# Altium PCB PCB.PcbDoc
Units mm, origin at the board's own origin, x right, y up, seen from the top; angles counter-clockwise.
Board outline 82.53 x 49.5 mm, 2 copper layers (Top Layer, Bottom Layer); 57 components, 42 nets, 216 pads, 120 vias.
Unrouted connection lines stored in the file: 2.
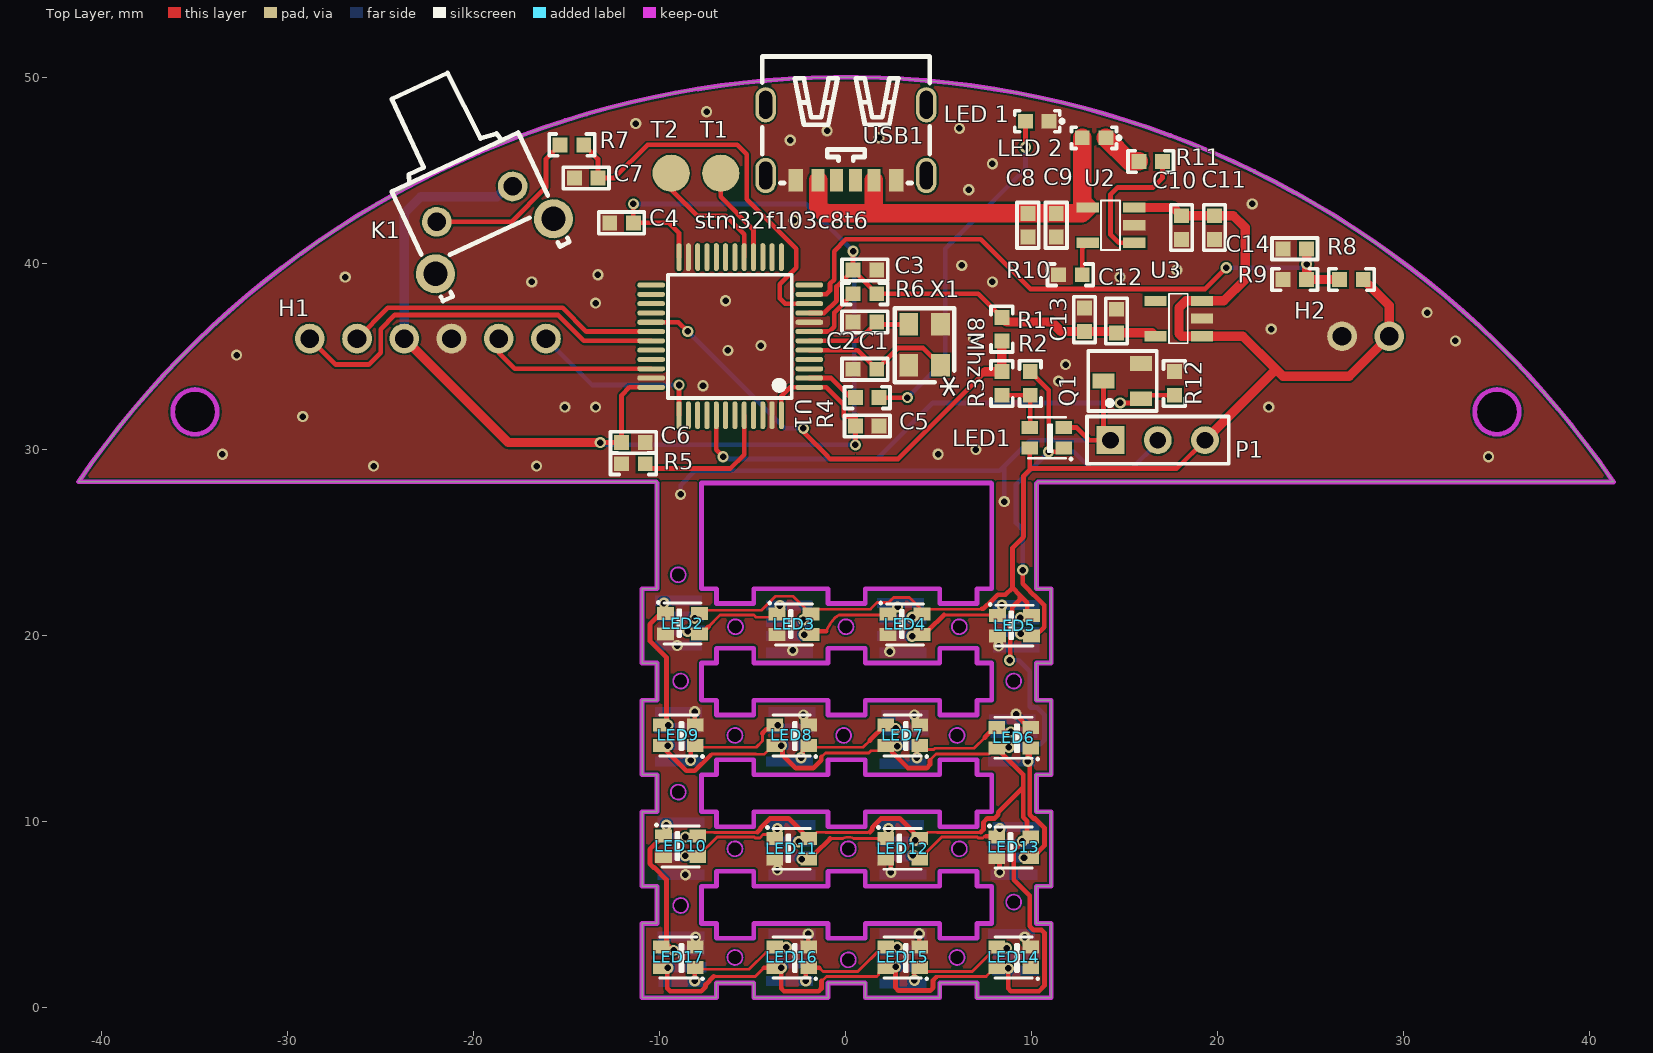
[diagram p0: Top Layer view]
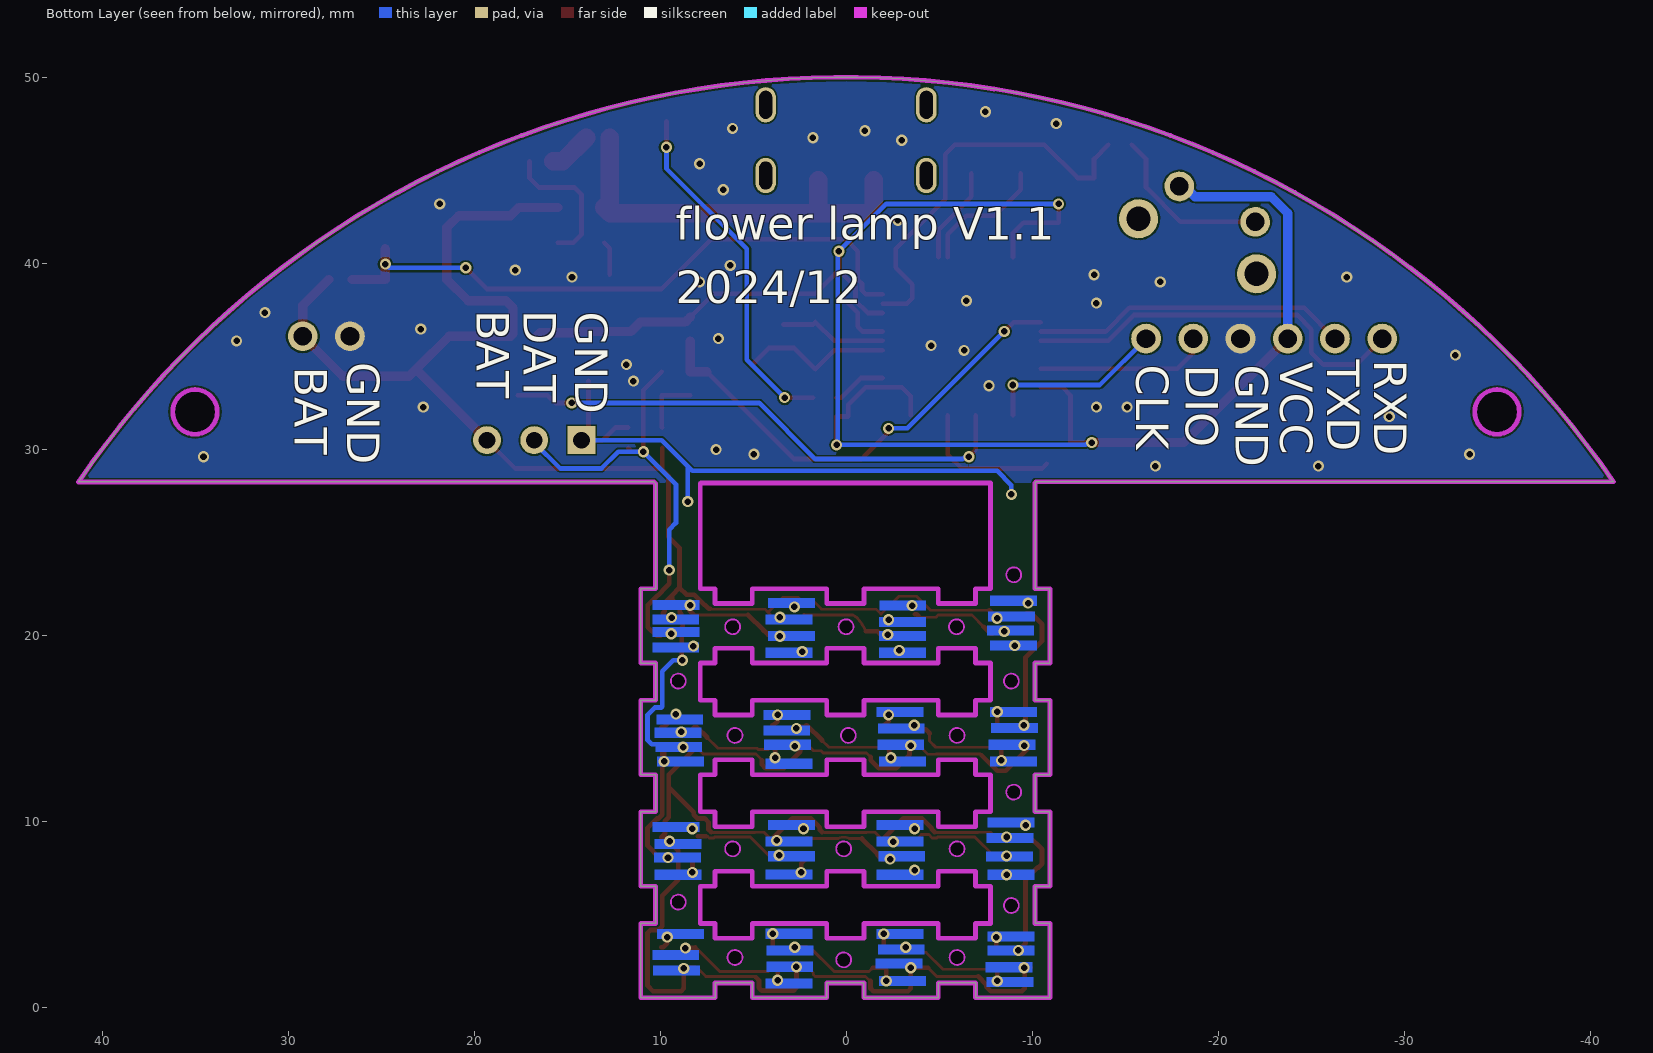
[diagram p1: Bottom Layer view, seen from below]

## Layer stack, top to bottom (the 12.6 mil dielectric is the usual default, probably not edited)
Top Solder: solder mask 0.0102, Solder Resist, Dk 3.5
Top Layer: signal copper 0.0356
Dielectric 1: dielectric 0.32, FR-4, Dk 4.8
Bottom Layer: signal copper 0.0356
Bottom Solder: solder mask 0.0102, Solder Resist, Dk 3.5

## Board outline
-10.962,0.497 -10.962,4.497 -10.162,4.497 -10.162,6.497 -10.962,6.497 -10.962,10.497 -10.162,10.497 -10.162,12.497 -10.962,12.497 -10.962,16.497 -10.162,16.497 -10.162,18.497 -10.962,18.497 -10.962,22.497 -10.162,22.497 -10.162,28.192 -10.206,28.236 -41.264,28.236 cw(c0,0) 41.266,28.233 10.326,28.233 10.238,28.145 10.238,22.497 11.038,22.497 11.038,18.497 10.238,18.497 10.238,16.497 11.038,16.497 11.038,12.497 10.238,12.497 10.238,10.497 11.038,10.497 11.038,6.497 10.238,6.497 10.238,4.497 11.038,4.497 11.038,0.497 7.038,0.497 7.038,1.297 5.038,1.297 5.038,0.497 1.038,0.497 1.038,1.297 -0.962,1.297 -0.962,0.497 -4.962,0.497 -4.962,1.297 -6.962,1.297 -6.962,0.497
cut-out: -9.417,23.241 ccw(c-9.017,23.241) -9.017,22.841 ccw(c-9.017,23.241) -8.617,23.241 ccw(c-9.017,23.241) -9.017,23.641 ccw(c-9.017,23.241)
cut-out: -0.273,2.54 ccw(c0.127,2.54) 0.127,2.14 ccw(c0.127,2.54) 0.527,2.54 ccw(c0.127,2.54) 0.127,2.94 ccw(c0.127,2.54)
cut-out: -6.369,2.667 ccw(c-5.969,2.667) -5.969,2.267 ccw(c-5.969,2.667) -5.569,2.667 ccw(c-5.969,2.667) -5.969,3.067 ccw(c-5.969,2.667)
cut-out: 5.569,2.667 ccw(c5.969,2.667) 5.969,2.267 ccw(c5.969,2.667) 6.369,2.667 ccw(c5.969,2.667) 5.969,3.067 ccw(c5.969,2.667)
cut-out: 8.617,5.644 ccw(c9.017,5.644) 9.017,5.244 ccw(c9.017,5.644) 9.417,5.644 ccw(c9.017,5.644) 9.017,6.044 ccw(c9.017,5.644)
cut-out: 5.696,8.509 ccw(c6.096,8.509) 6.096,8.109 ccw(c6.096,8.509) 6.496,8.509 ccw(c6.096,8.509) 6.096,8.909 ccw(c6.096,8.509)
cut-out: -0.273,8.509 ccw(c0.127,8.509) 0.127,8.109 ccw(c0.127,8.509) 0.527,8.509 ccw(c0.127,8.509) 0.127,8.909 ccw(c0.127,8.509)
cut-out: -6.369,8.509 ccw(c-5.969,8.509) -5.969,8.109 ccw(c-5.969,8.509) -5.569,8.509 ccw(c-5.969,8.509) -5.969,8.909 ccw(c-5.969,8.509)
cut-out: 8.617,17.526 ccw(c9.017,17.526) 9.017,17.126 ccw(c9.017,17.526) 9.417,17.526 ccw(c9.017,17.526) 9.017,17.926 ccw(c9.017,17.526)
cut-out: 5.569,14.605 ccw(c5.969,14.605) 5.969,14.205 ccw(c5.969,14.605) 6.369,14.605 ccw(c5.969,14.605) 5.969,15.005 ccw(c5.969,14.605)
cut-out: -0.527,14.605 ccw(c-0.127,14.605) -0.127,14.205 ccw(c-0.127,14.605) 0.273,14.605 ccw(c-0.127,14.605) -0.127,15.005 ccw(c-0.127,14.605)
cut-out: -6.369,14.605 ccw(c-5.969,14.605) -5.969,14.205 ccw(c-5.969,14.605) -5.569,14.605 ccw(c-5.969,14.605) -5.969,15.005 ccw(c-5.969,14.605)
cut-out: -9.29,5.461 ccw(c-8.89,5.461) -8.89,5.061 ccw(c-8.89,5.461) -8.49,5.461 ccw(c-8.89,5.461) -8.89,5.861 ccw(c-8.89,5.461)
cut-out: -9.417,11.557 ccw(c-9.017,11.557) -9.017,11.157 ccw(c-9.017,11.557) -8.617,11.557 ccw(c-9.017,11.557) -9.017,11.957 ccw(c-9.017,11.557)
cut-out: -9.29,17.526 ccw(c-8.89,17.526) -8.89,17.126 ccw(c-8.89,17.526) -8.49,17.526 ccw(c-8.89,17.526) -8.89,17.926 ccw(c-8.89,17.526)
cut-out: 5.696,20.447 ccw(c6.096,20.447) 6.096,20.047 ccw(c6.096,20.447) 6.496,20.447 ccw(c6.096,20.447) 6.096,20.847 ccw(c6.096,20.447)
cut-out: -0.4,20.447 ccw(c0,20.447) 0,20.047 ccw(c0,20.447) 0.4,20.447 ccw(c0,20.447) 0,20.847 ccw(c0,20.447)
cut-out: -6.34,20.447 ccw(c-5.94,20.447) -5.94,20.047 ccw(c-5.94,20.447) -5.54,20.447 ccw(c-5.94,20.447) -5.94,20.847 ccw(c-5.94,20.447)
cut-out: 33.8,32 ccw(c35,32) 35,30.8 ccw(c35,32) 36.2,32 ccw(c35,32) 35,33.2 ccw(c35,32)
cut-out: -35,30.8 cw(c-35,32) -36.2,32 cw(c-35,32) -35,33.2 cw(c-35,32) -33.8,32 cw(c-35,32)
cut-out: -6.962,21.697 -4.962,21.697 -4.962,22.497 -0.962,22.497 -0.962,21.697 1.038,21.697 1.038,22.497 5.038,22.497 5.038,21.697 7.038,21.697 7.038,22.497 7.838,22.497 7.838,28.158 7.817,28.179 -7.762,28.179 -7.762,22.497 -6.962,22.497
cut-out: -7.762,4.497 -6.962,4.497 -6.962,3.697 -4.962,3.697 -4.962,4.497 -0.962,4.497 -0.962,3.697 1.038,3.697 1.038,4.497 5.038,4.497 5.038,3.697 7.038,3.697 7.038,4.497 7.838,4.497 7.838,6.497 7.038,6.497 7.038,7.297 5.038,7.297 5.038,6.497 1.038,6.497 1.038,7.297 -0.962,7.297 -0.962,6.497 -4.962,6.497 -4.962,7.297 -6.962,7.297 -6.962,6.497 -7.762,6.497
cut-out: -4.962,9.697 -4.962,10.497 -0.962,10.497 -0.962,9.697 1.038,9.697 1.038,10.497 5.038,10.497 5.038,9.697 7.038,9.697 7.038,10.497 7.838,10.497 7.838,12.497 7.038,12.497 7.038,13.297 5.038,13.297 5.038,12.497 1.038,12.497 1.038,13.297 -0.962,13.297 -0.962,12.497 -4.962,12.497 -4.962,13.297 -6.962,13.297 -6.962,12.497 -7.762,12.497 -7.762,10.497 -6.962,10.497 -6.962,9.697
cut-out: -7.762,16.497 -6.962,16.497 -6.962,15.697 -4.962,15.697 -4.962,16.497 -0.962,16.497 -0.962,15.697 1.038,15.697 1.038,16.497 5.038,16.497 5.038,15.697 7.038,15.697 7.038,16.497 7.838,16.497 7.838,18.497 7.038,18.497 7.038,19.297 5.038,19.297 5.038,18.497 1.038,18.497 1.038,19.297 -0.962,19.297 -0.962,18.497 -4.962,18.497 -4.962,19.297 -6.962,19.297 -6.962,18.497 -7.762,18.497

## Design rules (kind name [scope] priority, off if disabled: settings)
Clearance [All] p1: gap=0.1 ignorepadtopadclearanceinfootprint=FALSE except(0: Arc-Hole Track-Hole SMDPad-Hole THPad-Hole Via-Hole Fill-Hole Poly-Hole Region-Hole Text-Hole; 0.102: Arc-Arc Arc-Track Arc-SMDPad Arc-THPad Track-Track Track-SMDPad Track-THPad SMDPad-SMDPad SMDPad-THPad THPad-THPad; 0.127: Arc-Via Track-Via SMDPad-Via SMDPad-Text THPad-Via Via-Via; 0.254: Arc-Text Track-Text THPad-Text Via-Text Fill-Text Poly-Text Region-Text Text-Text)
DiffPairsRouting [All] p1: maxlimit=0.254 minlimit=0.15 mostfreqgap=0.254 toplayer_minwidth=0.2 toplayer_maxwidth=0.381 toplayer_prefwidth=0.25 bottomlayer_minwidth=0.2 bottomlayer_maxwidth=0.381 bottomlayer_prefwidth=0.25 maxuncoupledlength=12.7
HoleSize [All] p1: absolutevalues=TRUE maxlimit=30 minlimit=0.025 maxpercent=80.000 minpercent=20.000
HoleToHoleClearance [All] p1: gap=0.152 allowstackedmicrovias=TRUE
MinimumSolderMaskSliver [All] p1: minsoldermaskwidth=0
PlaneClearance [All] p1: clearance=0.254
PlaneConnect [All] p1: planeconnectstyle=Direct reliefexpansion=0.508 reliefentries=4 reliefconductorwidth=0.254 reliefairgap=0.254
PolygonConnect [All] p1: connectstyle=Direct reliefconductorwidth=0.254 reliefentries=4 polygonreliefangle="90 Angle" airgapwidth=0.254
RoutingVias [All] p1: holewidth=0.711 width=1.27 viastyle="Through Hole" minholewidth=0.3 minwidth=0.5 maxholewidth=30 maxwidth=30
SilkToSilkClearance [All] p1: silktosilkclearance=0
SilkToSolderMaskClearance [IsPad] p1: minsilkscreentomaskgap=0 clearancetoexposedcopper=TRUE
SolderMaskExpansion [All] p1: expansion=0.102 istentingtop=FALSE
Width [All] p1: maxlimit=3 minlimit=0.1 preferedwidth=0.254
22 further rules are at their usual default settings.

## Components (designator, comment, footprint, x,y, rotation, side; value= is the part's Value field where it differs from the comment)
C1 "12pF" CC1608-0603 1.016,34.29 r0 top
C2 "12pF" CC1608-0603 1.016,36.83 r0 top
C3 "100NF" CC1608-0603 1.016,39.624 r180 top
C4 "100NF" CC1608-0603 -12.065,42.164 r0 top
C5 "100NF" CC1608-0603 1.143,31.242 r180 top
C6 "100NF" CC1608-0603 -11.43,30.353 r180 top
C7 "12pF" CC1608-0603 -13.97,44.577 r0 top
C8 "1UF" CC1608-0603 9.779,42.037 r90 top
C9 "100NF" CC1608-0603 11.303,42.037 r90 top
C10 "1UF" CC1608-0603 18.034,41.91 r90 top
C11 "100NF" CC1608-0603 19.812,41.91 r90 top
C12 "1UF" CC1608-0603 14.544,36.885 r270 top
C13 "100NF" CC1608-0603 12.827,36.957 r270 top
C14 "100PF" CC1608-0603 24.13,40.767 r0 top
H1 "Header_6P_Curved" Header_2_54_6PW -28.829,35.941 r0 top
H2 "Header_2P_Curved" Header_2_54_2PW 26.67,36.068 r0 top
K1 "SW-TH_4P_H" SW-TH_KH-6X6X7H-ZJ -19.431,42.037 r25 top locked
LED1 "WS2812B-2020" WS2812B-2020 10.795,30.607 r180 top
LED2 "WS2812B-2020" WS2812B-2020 -8.789,20.616 r0 top
LED3 "WS2812B-2020" WS2812B-2020 -2.794,20.574 r0 top
LED4 "WS2812B-2020" WS2812B-2020 3.175,20.574 r0 top
LED5 "WS2812B-2020" WS2812B-2020 9.061,20.507 r0 top
LED6 "WS2812B-2020" WS2812B-2020 9.017,14.478 r180 top
LED7 "WS2812B-2020" WS2812B-2020 3.048,14.605 r180 top
LED8 "WS2812B-2020" WS2812B-2020 -2.921,14.605 r180 top
LED9 "WS2812B-2020" WS2812B-2020 -9.017,14.605 r180 top
LED10 "WS2812B-2020" WS2812B-2020 -8.89,8.636 r0 top
LED11 "WS2812B-2020" WS2812B-2020 -2.921,8.509 r0 top
LED12 "WS2812B-2020" WS2812B-2020 3.048,8.509 r0 top
LED13 "WS2812B-2020" WS2812B-2020 9.017,8.585 r0 top
LED14 "WS2812B-2020" WS2812B-2020 9.017,2.667 r180 top
LED15 "WS2812B-2020" WS2812B-2020 3.048,2.667 r180 top
LED16 "WS2812B-2020" WS2812B-2020 -2.921,2.667 r180 top
LED17 "WS2812B-2020" WS2812B-2020 -9.017,2.667 r180 top
"LED 1" "LED 0603" "LED 0603" 10.287,47.625 r0 top
"LED 2" "LED 0603" "LED 0603" 13.335,46.736 r0 top
P1 "Header 3" HDR1X3 14.224,30.48 r0 top
Q1 "SI2302" SOT-23 15.863,32.705 r90 top
R1 "10K" CR1608-0603 8.382,36.449 r270 top
R2 "0R" CR1608-0603 9.906,33.528 r90 top
R3 "0R" CR1608-0603 8.382,33.528 r270 top
R4 "1K" CR1608-0603 1.143,32.766 r180 top
R5 "10K" CR1608-0603 -11.43,29.21 r0 top
R6 "10K" CR1608-0603 1.016,38.354 r180 top
R7 "1K" CR1608-0603 -14.732,46.355 r180 top
R8 "10K" CR1608-0603 27.178,39.116 r0 top
R9 "10K" CR1608-0603 24.13,39.116 r0 top
R10 "2K" CR1608-0603 12.065,39.37 r0 top
R11 "2K" CR1608-0603 16.383,45.466 r180 top
R12 "10K" CR1608-0603 17.653,33.528 r90 top
T1 "test" test -6.731,44.831 r0 top
T2 "test" test -9.398,44.831 r0 top
U1 "STM32F103C8T6" LQFP-48 -6.223,36.068 r90 top locked
U2 "TP4054" SOT23-5 15.494,42.992 r270 top
U3 "RT9013-33GB" SOT23-5 19.137,37.973 r270 top
USB1 "TYPE_C_SMD_6P" TYPE-C-SMD_TYPE-C-6P 0,46.482 r180 top locked
X1 "3225_8M" XTAL-3225 3.38,34.503 r90 top

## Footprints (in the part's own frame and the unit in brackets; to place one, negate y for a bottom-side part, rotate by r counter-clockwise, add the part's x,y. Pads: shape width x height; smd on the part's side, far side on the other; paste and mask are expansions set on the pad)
CC1608-0603 [mm]
  rect 0.8x0.8 smd: 1(-0.635,0) 2(0.635,0)
  silkscreen extent -1.23,-0.58 1.23,0.58, body extent -0.8,-0.4 0.8,0.4, height 0.3
CR1608-0603 [mm]
  rect 0.8x0.8 smd: 1(-0.635,0) 2(0.635,0)
  silkscreen extent -1.23,-0.58 1.23,0.58, body extent -0.8,-0.4 0.8,0.4, height 0.45
HDR1X3 [mm] "Connector; Header; 3 Position"
  rect 1.5x1.5 hole 0.9: 1(0,0)
  round 1.5 hole 0.9: 2(2.54,0) 3(5.08,0)
  silkscreen extent -1.27,-1.27 6.35,2.14, body extent -1.27,-1.27 6.35,1.27, height 8.54
Header_2_54_2PW [mm] "弯的排针"
  round 1.6 hole 1: 1(0,0) 2(2.54,0)
  body extent -2.52,-7.47 5.18,0.38, height 5.8
Header_2_54_6PW [mm] "6P弯针"
  round 1.6 hole 1: 1(0,0) 2(2.54,0) 3(5.08,0) 4(7.62,0) 5(10.16,0) 6(12.7,0)
  body extent -2.56,-7.48 15.3,0.37, height 5.8
"LED 0603" [mm]
  rect 0.8x0.8 smd: 1(-0.635,0) 2(0.635,0)
  silkscreen extent -1.21,-0.57 1.4,0.57, body extent -0.8,-0.4 0.8,0.4, height 0.6
LQFP-48 [mm]
  oval 0.27x1.5 smd: 1(-2.75,-4.25) 2(-2.25,-4.25) 3(-1.75,-4.25) 4(-1.25,-4.25) 5(-0.75,-4.25) 6(-0.25,-4.25) 7(0.25,-4.25) 8(0.75,-4.25) 9(1.25,-4.25) 10(1.75,-4.25) 11(2.25,-4.25) 12(2.75,-4.25) 25(2.75,4.25) 26(2.25,4.25) 27(1.75,4.25) 28(1.25,4.25) 29(0.75,4.25) 30(0.25,4.25) 31(-0.25,4.25) 32(-0.75,4.25) 33(-1.25,4.25) 34(-1.75,4.25) 35(-2.25,4.25) 36(-2.75,4.25)
  oval 1.5x0.27 smd: 13(4.25,-2.75) 14(4.25,-2.25) 15(4.25,-1.75) 16(4.25,-1.25) 17(4.25,-0.75) 18(4.25,-0.25) 19(4.25,0.25) 20(4.25,0.75) 21(4.25,1.25) 22(4.25,1.75) 23(4.25,2.25) 24(4.25,2.75) 37(-4.25,2.75) 38(-4.25,2.25) 39(-4.25,1.75) 40(-4.25,1.25) 41(-4.25,0.75) 42(-4.25,0.25) 43(-4.25,-0.25) 44(-4.25,-0.75) 45(-4.25,-1.25) 46(-4.25,-1.75) 47(-4.25,-2.25) 48(-4.25,-2.75)
  silkscreen extent -3.33,-3.31 3.3,3.34, body extent -4.47,-4.54 4.53,4.46, height 1.56
SOT23-5 [mm] "适用于MIC5205"
  rect 0.55x1.2 smd: 1(1.905,0) 2(0.955,0) 3(0.005,0) 4(0.005,-2.5) 5(1.905,-2.5)
  silkscreen extent -0.38,-1.78 2.29,-0.76, body extent -0.6,-2.82 2.5,0.38, height 1.45
SOT-23 [mm]
  rect 0.8x1.2 smd: 1(0,0) 2(1.905,0) 3(0.95,2.02)
  silkscreen extent -0.66,-0.84 2.57,2.84, body extent -0.61,-0.23 2.39,2.27, height 1.05
SW-TH_KH-6X6X7H-ZJ [mm]
  round 1.6 hole 1 paste+0 mask+0.05: 1(2.25,1.25) 2(-2.25,1.25)
  round 2.1 hole 1.3 paste+0 mask+0.05: 3(3.5,-1.25) 4(-3.5,-1.25)
  silkscreen extent -3.75,-2.75 3.75,8.25, body extent -3.75,-2.48 3.75,5.67, height 7.5
test [mm]
  round 2 smd: 0(0,0)
TYPE-C-SMD_TYPE-C-6P [mm]
  oval 1.1x1.9 hole 0.7 slot 1.5 at 90 deg paste+0 mask+0.051: 7(-4.32,-2.025) 7(-4.32,1.775) 7(4.32,-2.025) 7(4.32,1.775)
  rect 0.7x1.2 smd paste-100 mask+0.051: A5(-0.5,2.025) A9(1.5,2.025) B5(0.5,2.025) B9(-1.5,2.025)
  rect 0.8x1.2 smd paste-100 mask+0.051: A12(2.7,2.025) B12(-2.7,2.025)
  silkscreen extent -4.5,-4.63 4.5,2.18, body extent -4.44,-4.47 4.49,2.43, height 3.18
WS2812B-2020 [mm]
  rect 0.9x0.7 smd paste+0 mask+0.051: 1(-0.915,0.55) 2(-0.915,-0.55) 3(0.915,-0.55) 4(0.915,0.55)
  silkscreen extent -1.3,-1.1 1,1.15, body extent -1.1,-1 1.1,1, height 0.84
XTAL-3225 [mm]
  rect 1.2x1 smd: 1(0,-1.7) 2(2.2,-1.7) 3(2.2,0) 4(0,0)
  silkscreen extent -0.91,-2.44 3.07,0.76, body extent -0.43,-2.15 2.77,0.35, height 0.61

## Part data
C1 C2 C3 C4 C5 C6 C7 C8 C9 C10 C11 C12 C13 C14: library part "Cap Chip 0603", "0603封装的电容"
H1: "弯的6P排针"
H2: "弯的2P排针"
K1: "卧式轻触开关"
LED1 LED2 LED3 LED4 LED5 LED6 LED7 LED8 LED9 LED10 LED11 LED12 LED13 LED14 LED15 LED16 LED17: JLCPCB Part Class="Extended Part", Manufacturer=worldsemi
P1: "Header, 3-Pin"
Q1: "N沟道  / 漏源电压(Vdss) 20V  / 连续漏极电流(Id) 2.8A  / 功率(Pd) 900mW  / 导通电阻(RDS(on)@Vgs,Id) 55mΩ@4.5V,2.8A  / 阈值电压(Vgs(th)@Id) 1.2V@250uA  / 输入电容(Ciss@Vds) 260pF@10V", JLCPCB Part Class="Extended Part", Manufacturer=TWGMC(台湾迪嘉), Manufacturer Part=SI2306
R1 R2 R3 R4 R5 R6 R7 R8 R9 R10 R11 R12: library part "Resistor Chip 0603", "0603封装电阻"
T1 T2: "测试点"
U1: JLCPCB Part Class="Basic Part", Manufacturer=ST(意法半导体)
U2: "迷你充电IC SOT-23-5"
U3: "LDO 2.2-5.2V IN 500Ma OUT SOT23-5"
USB1: JLCPCB Part Class="Extended Part", Manufacturer=null
X1: library part "XTAL 3225", "3225封装的晶振"

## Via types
v1: diameter 0.6, hole 0.35, Top Layer to Bottom Layer, tented both sides, 120 vias

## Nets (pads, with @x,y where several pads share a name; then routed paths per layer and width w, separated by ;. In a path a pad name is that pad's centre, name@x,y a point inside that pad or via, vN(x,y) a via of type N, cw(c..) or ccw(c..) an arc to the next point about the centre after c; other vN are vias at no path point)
5V: "LED 2.1" C8.2 C9.2 U2.4 USB1.A9 USB1.B9 | length 22
  Top Layer w1: USB1.A9 -1.5,43.029 -1.143,42.672 1.778,42.672 ; USB1.B9 1.5,42.95 1.778,42.672 ; 12.7,46.736 12.7,43.281 U2.4 12.679,42.672 C9.2 C8.2 1.778,42.672
ADCIN1: C14.2 R8.1 R9.2 U1.11 | length 34.2
  Top Layer w0.254: U1.11 -1.052,38.318 -0.864,38.506 -0.864,38.882 -0.635,39.111 -0.635,40.64 0,41.275 7.239,41.275 9.906,38.608 19.304,38.608 v1(20.447,39.751)
  Top Layer w0.5: C14.2 v1(24.765,39.941) R9.2 R8.1
  Bottom Layer w0.254: v1(20.447,39.751) 24.575,39.751 v1(24.765,39.941)
BAT: C10.2 C11.2 H2.2 LED1.4 LED2.4 LED3.4 LED4.4 LED5.4 LED6.4 LED7.4 LED8.4 LED9.4 LED10.4 LED11.4 LED12.4 LED13.4 LED14.4 LED15.4 LED16.4 LED17.4 P1.3 R8.2 U2.3 U3.1 U3.3 | length 175.3
  Top Layer w0.15: LED10.4 -7.763,9.398 -7.092,9.398 -7.088,9.393 -4.836,9.393 -4.832,9.398 -4.758,9.398 ; LED2.4@-7.704,21.336 -4.547,21.336 -3.793,22.089 -2.844,22.089 LED3.4 -1.61,21.393 1.313,21.393 1.665,21.746 2.297,21.746 2.57,22.018 3.406,22.018 LED4.4@4.195,21.229 ; -7.302,13.525 -7.227,13.601 -4.836,13.601 -4.825,13.589 -4.402,13.589 -3.936,14.055 LED8.4 ; -7.111,1.651 -4.879,1.651 -4.413,2.117 ; LED11.4 -1.906,9.059 -1.567,9.398 -1.092,9.398 -1.088,9.393 1.164,9.393 1.168,9.398 1.286,9.398 ; -1.327,13.443 -1.104,13.666 1.222,13.666 1.335,13.78 1.758,13.78 2.033,14.055 LED7.4 ; -1.318,1.397 -1.291,1.397 -1.037,1.651 1.667,1.651 1.758,1.742 1.758,1.842 2.033,2.117 LED15.4 ; LED12.4 4.063,9.059 4.402,9.398 4.908,9.398 4.912,9.393 7.164,9.393 7.168,9.398 7.242,9.398 ; LED4.4 LED4.4@4.195,21.229 ; 4.513,13.275 4.839,13.601 7.675,13.601 8.002,13.928 LED6.4 ; 4.848,1.601 4.898,1.651 7.536,1.651 8.002,2.117 LED14.4 ; 7.294,21.413 7.274,21.393 4.359,21.393 LED4.4@4.195,21.229
  Top Layer w0.254: LED17.4 -9.832,2.117 -9.609,1.894 -9.609,1.001 -9.46,0.853 -7.783,0.853 -7.55,1.086 -7.55,1.211 -7.111,1.651 ; LED9.4 -8.577,12.7 -8.128,12.7 -7.302,13.525 ; LED2.4 LED2.4@-7.704,21.336 ; -4.758,9.398 -4.606,9.55 -4.606,9.618 -4.083,10.141 -3.088,10.141 LED11.4@-1.964,9.017 ; -4.413,2.117 LED16.4 v1(-3.481,2.117) -3.481,1.001 -3.332,0.853 -1.466,0.853 -1.318,1.001 -1.318,1.397 ; LED8.4 v1(-3.481,14.055) -3.415,13.989 -3.415,13.575 -2.693,12.853 -1.752,12.853 -1.327,13.278 -1.327,13.443 ; 1.286,9.398 1.331,9.443 1.394,9.505 cw(c1.739,9.505) 1.494,9.749 1.886,10.141 2.881,10.141 LED12.4 3.868,8.964 v1(3.728,8.964) ; LED15.4 2.154,2.138 2.646,2.138 v1(2.667,2.159) 2.667,1.038 2.816,0.889 4.534,0.889 4.682,1.038 4.682,1.444 4.84,1.601 4.848,1.601 ; v1(2.743,14.03) 2.731,14.042 2.245,14.042 2.456,13.832 2.456,13.732 3.335,12.853 4.344,12.853 4.513,13.022 4.513,13.275 ; 7.242,9.398 7.394,9.55 7.394,9.934 7.601,10.141 7.985,10.141 8.194,10.35 8.194,10.48 9.527,11.813 ; 7.294,21.413 7.378,21.413 7.601,21.636 7.631,21.636 8.157,22.161 8.572,22.161 8.954,22.543 ; LED14.4 8.202,2.117 8.223,2.096 v1@8.699,2.096 ; v1(8.721,2.074) 8.721,1.001 8.869,0.853 10.378,0.853 10.668,1.143 10.668,3.993 10.519,4.141 10.091,4.141 9.882,4.35 9.882,5.993 9.017,6.858 9.017,8.414 9.482,8.879 v1(9.482,8.912) ; v1(8.763,13.97) 8.624,13.97 8.603,13.949 8.123,13.949 LED6.4 9.527,12.503 9.527,11.813 ; v1(8.794,18.65) 8.825,18.681 8.825,20.402 8.782,20.444 8.782,20.57 8.871,20.658 8.871,21.146 8.94,21.216 8.94,21.486 9.353,21.899 9.353,22.143 ; v1(9.379,20.936) 9.439,20.997 9.682,20.997 9.859,21.174 9.753,21.28 9.753,21.743 9.353,22.143 ; LED13.4@9.705,9.135 LED13.4@9.609,9.039 ; LED13.4@9.805,9.135 LED13.4 9.736,9.331 9.736,9.993 9.527,10.202 9.527,11.813 ; 9.88,28.956 17.78,28.956 P1.3 ; LED1.4 9.88,28.89 9.819,28.829 9.545,28.555 9.545,25.293 8.954,24.701 8.954,22.543 ; 8.954,22.543 9.353,22.143 ; v1(9.482,8.912) 9.609,8.912 LED13.4@9.609,9.039 ; v1(9.482,8.912) LED13.4@9.609,9.039
  Top Layer w0.5: U2.3 17.592,42.987 C10.2 C11.2 20.828,42.545 21.463,41.91 21.463,39.116 20.315,37.968 U3.3 18.283,37.968 17.907,37.592 17.907,36.195 18.034,36.068 U3.1 21.336,36.068 23.05,34.353 ; P1.3 23.05,34.227 23.05,34.353 ; R8.2 29.21,37.719 H2.2 27.051,33.909 23.495,33.909 23.05,34.353
  Bottom Layer w0.254: -8.898,20.995 -8.206,20.995 v1(-8.119,20.907) ; v1(2.743,14.03) 3.073,14.03 3.149,14.105 ; 3.199,8.959 3.204,8.964 v1(3.728,8.964) ; v1(8.794,18.65) 9.29,18.65 9.882,18.058 9.882,16.153 9.933,16.102 10.284,16.102 10.668,15.718 10.668,14.351 10.445,14.128 9.567,14.128 ; v1@9.136,20.907 9.35,20.907 v1(9.379,20.936)
  other v1: -9.577,2.117 -2.54,8.89 -8.636,9.144 -9.577,14.055 -2.286,20.828 3.556,20.955
BOOT0: R5.2 U1.44 | length 7.8
  Top Layer w0.254: R5.2 -10.541,28.956 -6.223,28.956 -5.473,29.706 U1.44
CFG_LED: Q1.1 R12.1 U1.41 | length 28.1
  Top Layer w0.254: U1.41 -6.973,29.96 v1(-6.604,29.591) ; v1(14.744,32.481) 15.64,32.481 16.051,32.893 R12.1
  Bottom Layer w0.254: v1(-6.604,29.591) -6.538,29.525 -6.343,29.525 -6.282,29.464 1.651,29.464 4.668,32.481 v1(14.744,32.481)
DO: LED1.1 LED5.3 P1.2 R2.2 | length 24.4
  Top Layer w0.254: v1(9.507,23.495) 9.507,22.762 9.882,22.388 9.882,22.35 10.091,22.141 10.129,22.141 10.655,21.615 10.655,20.434 10.178,19.957 LED5.3 ; R2.2 10.895,33.174 v1(10.895,29.857) 11.51,29.857 LED1.1
  Bottom Layer w0.254: v1@9.259,20.223 9.398,20.085 v1(9.398,20.075) ; v1(9.507,23.495) 9.507,25.666 9.144,26.029 9.144,28.106 v1(10.895,29.857) 12.249,29.857 13.15,28.956 15.367,28.956 16.764,30.353 P1.2
GND: "LED 1.2" C1.1 C2.1 C3.1 C4.1 C5.1 C6.1 C7.1 C8.1 C9.1 C10.1 C11.1 C12.1 C13.1 C14.1 H1.4 H2.1 Q1.2 R5.1 R9.1 R10.1 R12.2 U1.8 U1.23 U1.35 U1.47 U2.2 U3.2 USB1.A12 USB1.B12 X1.2 X1.4
  other v1: -25.4,29.083 -16.637,29.083 34.544,29.591 -33.528,29.718 4.953,29.718 6.985,29.972 -29.21,31.75 -15.113,32.258 -13.462,32.258 22.733,32.258 -7.687,33.409 11.43,33.655 11.811,34.544 -32.766,35.052 -6.35,35.306 -4.572,35.56 32.766,35.814 6.858,35.941 22.86,36.449 31.242,37.338 -13.462,37.846 -6.477,37.973 -16.891,38.989 7.874,38.989 -26.924,39.243 14.732,39.243 -13.335,39.37 17.78,39.624 6.223,39.878 -2.794,42.291 21.844,43.18 6.604,43.942 7.874,45.339 -3,46.607 1.778,46.736 -1.016,47.117 6.096,47.244 -11.303,47.498 -7.493,48.133
L_GND: LED1.2 LED2.2 LED3.2 LED4.2 LED5.2 LED6.2 LED7.2 LED8.2 LED9.2 LED10.2 LED11.2 LED12.2 LED13.2 LED14.2 LED15.2 LED16.2 LED17.2 P1.1 Q1.3 | length 40.4
  Top Layer w0.254: v1(-8.128,15.875) -8.128,15.181 LED9.2 ; LED17.2 -8.084,3.235 v1(-8.084,3.754) ; v1(-2.286,15.705) -2.286,15.378 -2.063,15.155 LED8.2 ; v1(-2.032,3.937) -2.032,3.243 LED16.2 ; LED12.2 2.19,7.959 2.413,7.736 v1(2.413,7.239) ; v1(3.683,15.705) 3.683,15.378 3.906,15.155 LED7.2 ; v1(3.937,3.943) 3.937,3.243 LED15.2 ; LED13.2 8.255,7.882 v1(8.255,7.239) ; v1(9.144,15.748) 9.144,15.716 9.832,15.028 LED6.2 ; v1(9.609,3.767) 9.609,3.44 9.832,3.217 LED14.2 ; LED1.2 12.404,31.157 13.081,30.48 P1.1 13.843,30.861 Q1.3
  Bottom Layer w0.254: v1(-8.89,27.559) -8.89,28.067 -8.128,28.829 8.255,28.829 8.509,29.083 ; v1(8.509,27.178) 8.509,29.083 ; P1.1 9.906,30.48 8.509,29.083
  other v1: -8.636,7.112 -3.683,7.366 2.35,19.114 -2.862,19.177 8.209,19.407 -9.069,19.431
LED0: R4.2 U1.2 | length 2.9
  Top Layer w0.254: U1.2 -0.798,33.818 0.254,32.766 R4.2
NetK1_2: K1.2 R7.2 | length 9.2
  Top Layer w0.254: K1.2 -17.979,42.219 -16.129,44.069 -16.129,45.593 R7.2
NetLED2_1: LED2.1 LED9.3 | length 7.7
  Top Layer w0.254: LED9.3 v1(-9.567,15.155) ; LED2.1 -9.949,21.166 -10.541,20.574 -10.541,19.685 -9.652,18.796 LED9.3@-9.652,15.24
  Bottom Layer w0.254: v1(-9.567,15.155) -9.417,15.005 -9.061,15.005
  other v1: -9.789,21.716
NetLED2_3: LED2.3 LED3.1 | length 4.7
  Top Layer w0.15: -7.393,20.447 -6.766,21.074 -4.945,21.074 -4.826,20.955 -3.978,20.955 LED3.1@-3.914,21.019
  Top Layer w0.254: LED2.3 -7.774,20.066 -7.393,20.447 ; LED3.1@-3.914,21.019 -3.809,21.124 LED3.1
  other v1: -8.509,20.193 -3.556,21.587
NetLED3_3: LED3.3 LED4.1 | length 4.9
  Top Layer w0.15: -1.066,20.199 cw(c1.031,19.337) -0.572,20.94 cw(c-0.129,20.497) -0.367,21.077 -0.362,21.082 2.218,21.082 LED4.1
  Top Layer w0.254: LED3.3 -1.704,20.199 -1.066,20.199
  Bottom Layer w0.254: v1(2.778,21.516) 2.778,21.559 v1@2.936,21.717
  other v1: -2.244,20.024
NetLED4_3: LED4.3 LED5.1 | length 6.2
  Top Layer w0.15: 5.271,21.082 8.121,21.082 LED5.1
  Top Layer w0.254: LED4.3@3.709,20.024 4.213,20.024 4.213,20.047 4.413,20.247 4.436,20.247 5.271,21.082 ; LED5.1 8.321,21.232 8.338,21.232 8.386,21.28 v1(8.386,21.607)
  Bottom Layer w0.254: v1(8.386,21.607) 9.03,21.607
  other v1: 3.556,19.939
NetLED6_1: LED6.1 LED13.3 | length 7.3
  Top Layer w0.254: v1(9.571,8.035) LED13.3@9.807,8.035 ; v1(9.779,13.208) 9.779,13.361 9.779,13.775 LED6.1 ; v1@9.882,13.208 9.882,10.35 10.125,10.107 ; v1@9.882,13.361 LED6.1@9.882,13.775 ; LED13.3 10.032,8.035 10.668,8.671 10.668,9.633 10.16,10.141
NetLED6_3: LED6.3 LED7.1 | length 6.5
  Top Layer w0.15: LED7.1 4.175,13.843 4.725,13.843 4.8,13.918 6.892,13.918 7.473,14.499
  Top Layer w0.254: v1(3.81,13.407) 3.81,13.832 3.835,13.857 LED7.1@3.865,13.857 ; LED7.1@3.81,13.902 LED7.1 ; 7.473,14.499 8.002,15.028 8.192,15.028 8.361,14.859 8.791,14.859 v1(8.857,14.793)
  Bottom Layer w0.254: v1(8.857,14.793) 8.901,14.749 v1@9.028,14.749
NetLED7_3: LED7.3 LED8.1 | length 6.1
  Top Layer w0.15: LED8.1 -1.921,13.97 0.925,13.97 1.288,14.333
  Top Layer w0.254: v1(-2.413,13.407) -2.413,13.5 -2.329,13.584 -2.329,13.832 -2.106,14.055 LED8.1 ; 1.288,14.333 2.11,15.155 LED7.3 2.236,15.052 2.601,15.052 v1(2.667,14.986)
NetLED8_3: LED8.3 LED9.1 | length 5.9
  Top Layer w0.15: LED9.1 -8.017,13.97 -4.826,13.97 -4.493,14.303 -4.493,14.713
  Top Layer w0.254: v1(-8.353,13.259) -8.353,13.832 -8.13,14.055 LED9.1 ; -4.493,14.713 -4.274,14.932 -4.059,14.932 LED8.3
  other v1: -3.671,15.155
NetLED10_1: LED10.1 LED17.3 | length 7.7
  Top Layer w0.254: LED17.3 -9.829,3.114 -9.337,3.114 v1(-9.271,3.048) -9.652,3.429 -9.652,6.858 -10.301,7.507 -10.35,7.507 -10.541,7.699 -10.541,8.473 -9.828,9.186 LED10.1
  other v1: -9.652,9.779
NetLED10_3: LED10.3 LED11.1 | length 4.8
  Top Layer w0.15: LED10.3 -6.919,9.142 -4.931,9.142 -4.884,9.094 -4.632,9.094 -4.456,9.271 -4.048,9.271 LED11.1
  other v1: -8.636,8.128 -3.683,9.587
NetLED11_3: LED11.3 LED12.1 | length 4.7
  Top Layer w0.15: -0.857,9.059 -0.173,9.059 cw(c0.127,8.509) 0.427,9.059 LED12.1@2.033,9.059
  Top Layer w0.254: LED11.3 -1.906,7.959 -1.683,8.182 -1.683,8.233 -0.857,9.059 ; LED12.1@2.033,9.059 LED12.1
  other v1: -2.371,7.959 2.286,9.587
NetLED12_3: LED12.3 LED13.1 | length 4.6
  Top Layer w0.15: LED12.3 5.146,9.142 7.069,9.142 7.116,9.094 7.368,9.094 7.459,9.186 7.533,9.186
  Top Layer w0.254: 7.533,9.186 LED13.1@7.975,9.186
  other v1: 3.598,8.159 8.263,9.588
NetLED14_3: LED14.3 LED15.1 | length 6.2
  Top Layer w0.15: LED15.1@3.863,2.117 LED15.1 4.175,1.905 6.79,1.905 LED14.3
  Top Layer w0.254: v1(3.675,1.443) 3.675,1.929 LED15.1@3.863,2.117 ; LED14.3 8.123,3.196 8.615,3.196 v1(8.636,3.175)
NetLED15_3: LED15.3 LED16.1 | length 6.2
  Top Layer w0.15: -1.439,2.117 -1.227,1.905 0.635,1.905 1.947,3.217 LED15.3
  Top Layer w0.254: v1(-2.159,1.407) -2.159,2.021 -2.063,2.117 LED16.1 -1.439,2.117 ; LED15.3 2.137,3.213 2.139,3.215 2.754,3.215 v1(2.756,3.213)
NetLED16_3: LED16.3 LED17.1 | length 6.1
  Top Layer w0.15: LED17.1@-8.128,2.091 LED17.1 -8.017,2.032 -5.207,2.032 -4.297,2.942 -4.111,2.942 LED16.3
  Top Layer w0.254: v1(-8.128,1.407) LED17.1@-8.128,2.091 ; LED16.3 -3.835,3.216 v1(-3.214,3.214) v1(-3.214,3.214)
"NetLED 1_1": "LED 1.1" R4.1 | length 19
  Top Layer w0.254: R4.1 v1(3.302,32.766) ; v1(9.652,46.228) 9.652,47.625
  Bottom Layer w0.254: v1(3.302,32.766) 5.334,34.798 5.334,40.767 9.652,45.085 v1(9.652,46.228)
"NetLED 2_2": "LED 2.2" R11.2 | length 2.3
  Top Layer w1: 13.97,46.736 15.24,45.466 R11.2
NetR10_2: R10.2 U2.5 | length 1.8
  Top Layer w0.254: R10.2 12.7,40.793 U2.5
NetR11_1: R11.1 U2.1 | length 7.7
  Top Layer w0.254: U2.1 14.666,41.087 14.224,41.529 14.224,43.688 14.605,44.069 16.51,44.069 17.018,44.577 R11.1
NetT1_0: T1.0 U1.16 | length 5.2
  Top Layer w0.254: T1.0 -6.731,43.561 -4.973,41.803 U1.16
NetT2_0: T2.0 U1.17 | length 7
  Top Layer w0.254: T2.0 -9.398,43.942 -8.001,42.545 -6.477,42.545 -5.473,41.541 U1.17
NRST: R6.2 U1.7 | length 3.6
  Top Layer w0.254: U1.7 -0.893,36.318 -0.635,36.576 -0.635,37.338 R6.2
RCC_IN: C1.2 U1.5 X1.1 | length 8.3
  Top Layer w0.254: U1.5 0.623,35.318 C1.2 2.794,35.433 4.15,35.433 X1.1
RCC_OUT: C2.2 U1.6 X1.3 | length 5.8
  Top Layer w0.254: U1.6 0.639,35.818 C2.2 1.778,36.703 X1.3
RXD: H1.1 U1.31 | length 21.4
  Top Layer w0.254: H1.1 -27.432,34.544 -25.654,34.544 -25.019,35.179 -25.019,36.449 -24.257,37.211 -15.489,37.211 -14.096,35.818 U1.31
SWCLK: H1.6 U1.37 | length 9.8
  Top Layer w0.254: U1.37 v1(-8.973,33.445)
  Bottom Layer w0.254: H1.6 -13.633,33.445 v1(-8.973,33.445)
SWDIO: H1.5 U1.34 | length 9.3
  Top Layer w0.254: H1.5 -18.669,35.179 -17.808,34.318 U1.34
SYS_WKUP0: C7.2 R7.1 U1.10 | length 22
  Top Layer w0.254: R7.1 -13.335,45.593 C7.2 -12.446,44.577 -10.668,46.355 -5.842,46.355 -5.334,45.847 -5.334,43.434 -2.667,40.767 -2.667,39.751 -3.556,38.862 -3.556,38.1 -3.274,37.818 U1.10
TIM1CH1: R1.2 R3.1 U1.29 | length 25.6
  Top Layer w0.254: U1.29 -9.005,36.818 v1(-8.509,36.322) ; v1(-2.286,31.115) -2.22,31.049 -2.22,30.841 -1.099,29.72 -0.843,29.464 2.794,29.464 7.493,34.163
  Top Layer w0.5: 7.493,34.163 R3.1 R1.2
  Bottom Layer w0.254: v1(-8.509,36.322) -3.302,31.115 v1(-2.286,31.115)
TXD: H1.2 U1.30 | length 17
  Top Layer w0.254: H1.2 -24.638,37.592 -15.24,37.592 -13.966,36.318 U1.30
VCC: C3.2 C4.2 C5.2 C6.2 C12.2 C13.2 H1.3 K1.1 R1.1 R6.1 U1.1 U1.9 U1.24 U1.36 U1.48 U3.5 | length 103.8
  Top Layer w0.254: v1(-13.208,30.353) C6.2 -12.065,32.893 -11.64,33.318 U1.36 ; v1(-11.43,43.18) C4.2 -9.525,42.164 -8.973,41.612 U1.24 ; U1.48 -3.473,32.849 -3.004,33.318 U1.1 -1.06,33.318 -0.121,32.379 -0.121,31.75 0.508,31.75 v1(0.508,30.226) ; U1.9 -1.163,37.318 -0.508,37.973 -0.508,38.735 C3.2 ; v1(0.381,40.64) C3.2 ; R1.1 7.112,38.354 R6.1 C3.2
  Top Layer w0.5: H1.3 -18.161,30.353 v1(-13.208,30.353) ; R1.1 8.636,36.83 11.049,36.83 11.557,36.322 C13.2 14.472,36.322 C12.2 16.455,36.25 U3.5
  Bottom Layer w0.254: v1(-13.208,30.353) -13.142,30.287 -12.947,30.287 -12.886,30.226 v1(0.508,30.226) 0.445,30.29 0.445,40.576 -2.159,43.18 v1(-11.43,43.18)
  Bottom Layer w0.5: H1.3 -23.749,42.672 -22.86,43.561 -18.763,43.561 -18.203,44.121 K1.1
WS2812: LED1.3 R2.1 R3.2 | length 3.3
  Top Layer w0.254: R3.2 R2.1 9.906,31.183 LED1.3
pads on no net: K1.3 K1.4 LED14.1 U1.3 U1.4 U1.12 U1.13 U1.14 U1.15 U1.18 U1.19 U1.20 U1.21 U1.22 U1.25 U1.26 U1.27 U1.28 U1.32 U1.33 U1.38 U1.39 U1.40 U1.42 U1.43 U1.45 U1.46 U3.4 USB1.7 USB1.A5 USB1.B5

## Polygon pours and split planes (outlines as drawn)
no net on Bottom Solder "NONET_L-01_P-001" (solid): 7.366,4.318 10.668,4.318 10.668,1.143 7.493,1.143
no net on Bottom Solder "NONET_L-01_P-001" (solid): 1.397,4.191 4.699,4.191 4.699,1.054 4.534,0.889 1.524,0.889
no net on Bottom Solder "NONET_L-01_P-001" (solid): -4.572,4.191 -1.397,4.191 -1.392,4.186 -1.392,0.927 -4.356,0.927 -4.445,1.016
no net on Bottom Solder "NONET_L-01_P-001" (solid): -10.668,4.064 -7.239,4.064 -7.239,1.016 -7.366,0.889 -10.541,0.889
no net on Bottom Solder "NONET_L-01_P-001" (solid): 7.366,10.16 10.541,10.16 10.668,10.033 10.668,6.858 7.493,6.858
no net on Bottom Solder "NONET_L-01_P-001" (solid): 1.397,10.287 4.699,10.287 4.699,6.858 4.572,6.731 1.397,6.731
no net on Bottom Solder "NONET_L-01_P-001" (solid): -4.572,10.16 -1.27,10.16 -1.27,6.731 -4.572,6.731
no net on Bottom Solder "NONET_L-01_P-001" (solid): -10.668,10.16 -7.366,10.16 -7.366,6.858 -7.493,6.731 -10.541,6.731
no net on Bottom Solder "NONET_L-01_P-001" (solid): -10.541,16.256 -7.239,16.256 -7.239,12.827 -10.541,12.827
no net on Bottom Solder "NONET_L-01_P-001" (solid): -4.572,16.256 -1.397,16.256 -1.397,12.7 -4.445,12.7
no net on Bottom Solder "NONET_L-01_P-001" (solid): 1.524,16.129 4.572,16.129 4.572,12.827 1.524,12.827
no net on Bottom Solder "NONET_L-01_P-001" (solid): 7.493,15.875 10.057,15.875 10.317,15.615 10.317,12.924 10.414,12.827 10.287,12.7 7.493,12.7
no net on Bottom Solder "NONET_L-01_P-001" (solid): 7.366,22.098 10.795,22.098 10.795,18.923 10.668,18.796 7.366,18.796
no net on Bottom Solder "NONET_L-01_P-001" (solid): 1.397,22.225 4.699,22.225 4.699,18.796 1.27,18.796
no net on Bottom Solder "NONET_L-01_P-001" (solid): -4.572,22.098 -1.27,22.098 -1.27,18.796 -4.572,18.796
no net on Bottom Solder "NONET_L-01_P-001" (solid): -10.541,22.098 -7.366,22.098 -7.366,18.923 -10.541,18.923
GND on Bottom Layer "GND_L02_P002" (solid, remove dead copper, pour order 2): -10.162,28.192 -10.206,28.236 -41.264,28.236 cw(c0,0) 41.266,28.233 10.326,28.233 10.285,28.192
GND on Top Layer "GND_L01_P005" (solid, remove dead copper, pour order 5): -10.162,28.192 -10.206,28.236 -41.264,28.236 cw(c0,0) 41.266,28.233 10.326,28.233 10.285,28.192
L_GND on Top Layer "NONET_L-01_P-001" (solid, pour order 4): -10.184,28.214 -10.165,28.233 10.326,28.233 10.326,23.209 11.038,22.497 11.038,0.497 -11.292,0.497 -11.303,0.508 -10.962,0.849 -10.962,22.497

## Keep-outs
Keep-Out Layer:
  circle w0.1: c-9.017,23.241 r0.4
  circle w0.1: c-5.969,2.667 r0.4
  circle w0.1: c0.127,2.54 r0.4
  circle w0.1: c5.969,2.667 r0.4
  circle w0.1: c9.017,5.644 r0.4
  circle w0.1: c6.096,8.509 r0.4
  circle w0.1: c0.127,8.509 r0.4
  circle w0.1: c-5.969,8.509 r0.4
  circle w0.1: c9.017,17.526 r0.4
  circle w0.1: c5.969,14.605 r0.4
  circle w0.1: c-0.127,14.605 r0.4
  circle w0.1: c-5.969,14.605 r0.4
  circle w0.1: c-8.89,5.461 r0.4
  circle w0.1: c-9.017,11.557 r0.4
  circle w0.1: c-8.89,17.526 r0.4
  circle w0.1: c6.096,20.447 r0.4
  circle w0.1: c0,20.447 r0.4
  circle w0.1: c-5.94,20.447 r0.4
  circle w0.254: c35,32 r1.2
  circle w0.254: c-35,32 r1.2
  lines w0.254: -10.206,28.236 -41.264,28.236 cw(c0,0) 41.266,28.233 10.326,28.233 ; -10.162,28.192 -10.162,22.497 -10.962,22.497 -10.962,21.697 -10.962,19.297 -10.962,18.497 -10.162,18.497 -10.162,16.497 -10.962,16.497 -10.962,15.697 -10.962,13.297 -10.962,12.497 -10.162,12.497 -10.162,10.497 -10.962,10.497 -10.962,6.497 -10.162,6.497 -10.162,4.497 -10.962,4.497 -10.962,0.497 -10.162,0.497 -7.762,0.497 -6.962,0.497 -6.962,1.297 -4.962,1.297 -4.962,0.497 -0.962,0.497 -0.962,1.297 1.038,1.297 1.038,0.497 5.038,0.497 5.038,1.297 7.038,1.297 7.038,0.497 11.038,0.497 11.038,1.297 11.038,3.697 11.038,4.497 10.238,4.497 10.238,6.497 11.038,6.497 11.038,7.297 11.038,9.697 11.038,10.497 10.238,10.497 10.238,12.497 11.038,12.497 11.038,13.297 11.038,15.697 11.038,16.497 10.238,16.497 10.238,18.497 11.038,18.497 11.038,19.297 11.038,21.697 11.038,22.497 10.238,22.497 10.238,28.145 ; 7.817,28.179 -7.762,28.179 -7.762,22.497 -6.962,22.497 -6.962,21.697 -4.962,21.697 -4.962,22.497 -0.962,22.497 -0.962,21.697 1.038,21.697 1.038,22.497 5.038,22.497 5.038,21.697 7.038,21.697 7.038,22.497 7.838,22.497 7.838,28.158 ; -7.762,4.497 -7.762,6.497 -6.962,6.497 -6.962,7.297 -4.962,7.297 -4.962,6.497 -0.962,6.497 -0.962,7.297 1.038,7.297 1.038,6.497 5.038,6.497 5.038,7.297 7.038,7.297 7.038,6.497 7.838,6.497 7.838,4.497 7.038,4.497 7.038,3.697 5.038,3.697 5.038,4.497 1.038,4.497 1.038,3.697 -0.962,3.697 -0.962,4.497 -4.962,4.497 -4.962,3.697 -6.962,3.697 -6.962,4.497 -7.762,4.497 ; -7.762,10.497 -7.762,12.497 -6.962,12.497 -6.962,13.297 -4.962,13.297 -4.962,12.497 -0.962,12.497 -0.962,13.297 1.038,13.297 1.038,12.497 5.038,12.497 5.038,13.297 7.038,13.297 7.038,12.497 7.838,12.497 7.838,10.497 7.038,10.497 7.038,9.697 5.038,9.697 5.038,10.497 1.038,10.497 1.038,9.697 -0.962,9.697 -0.962,10.497 -4.962,10.497 -4.962,9.697 -6.962,9.697 -6.962,10.497 -7.762,10.497 ; -7.762,16.497 -6.962,16.497 -6.962,15.697 -4.962,15.697 -4.962,16.497 -0.962,16.497 -0.962,15.697 1.038,15.697 1.038,16.497 5.038,16.497 5.038,15.697 7.038,15.697 7.038,16.497 7.838,16.497 7.838,18.497 7.038,18.497 7.038,19.297 5.038,19.297 5.038,18.497 1.038,18.497 1.038,19.297 -0.962,19.297 -0.962,18.497 -4.962,18.497 -4.962,19.297 -6.962,19.297 -6.962,18.497 -7.762,18.497 -7.762,16.497

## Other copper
Bottom Layer:
  rectangle net BAT: 7.859,1.696 10.377,2.238
  rectangle net NetLED14_3: 7.9,2.523 10.418,3.065
  rectangle net L_GND: 7.646,3.666 10.164,4.208
  rectangle net NetLED14_3: 1.804,0.999 4.322,1.541
  rectangle net BAT: 1.765,1.896 4.283,2.438
  rectangle net NetLED15_3: 1.745,2.776 4.263,3.318
  rectangle net L_GND: 1.804,3.672 4.322,4.214
  rectangle net NetLED15_3: -4.292,1.136 -1.774,1.678
  rectangle net BAT: -4.104,2.071 -1.586,2.613
  rectangle net NetLED16_3: -4.224,2.816 -1.706,3.358
  rectangle net L_GND: -4.165,3.666 -1.647,4.208
  rectangle net NetLED16_3: -10.068,1.086 -7.55,1.628
  rectangle net BAT: -10.025,1.871 -7.507,2.413
  rectangle net L_GND: -10.138,3.522 -7.62,4.064
  rectangle net NetLED10_1: -10.134,2.777 -7.616,3.319
  rectangle net L_GND: -10.134,6.841 -7.616,7.383
  rectangle net NetLED10_3: -10.048,7.815 -7.53,8.357
  rectangle net BAT: -10.073,8.815 -7.555,9.357
  rectangle net NetLED10_1: -10.138,9.652 -7.62,10.194
  rectangle net NetLED10_3: -4.165,9.508 -1.647,10.05
  rectangle net BAT: -4.169,8.636 -1.651,9.178
  rectangle net NetLED11_3: -4.254,7.838 -1.736,8.38
  rectangle net L_GND: -4.165,6.841 -1.647,7.383
  rectangle net L_GND: 1.8,6.858 4.318,7.4
  rectangle net NetLED12_3: 1.665,7.838 4.183,8.38
  rectangle net BAT: 1.8,8.636 4.318,9.178
  rectangle net NetLED11_3: 1.673,9.525 4.191,10.067
  rectangle net L_GND: 7.773,6.841 10.291,7.383
  rectangle net NetLED6_1: 7.799,7.764 10.317,8.307
  rectangle net BAT: 7.773,8.492 10.291,9.034
  rectangle net NetLED12_3: 7.884,9.414 10.402,9.957
  rectangle net NetLED6_1: 7.646,12.937 10.164,13.479
  rectangle net BAT: 7.734,13.707 10.252,14.249
  rectangle net NetLED6_3: 7.769,14.478 10.287,15.02
  rectangle net L_GND: 7.679,15.193 10.197,15.735
  rectangle net NetLED6_3: 1.804,12.81 4.322,13.352
  rectangle net BAT: 1.89,13.834 4.408,14.376
  rectangle net NetLED7_3: 1.931,14.588 4.449,15.13
  rectangle net L_GND: 1.915,15.434 4.433,15.976
  rectangle net NetLED7_3: -4.292,12.937 -1.774,13.479
  rectangle net BAT: -4.204,13.834 -1.686,14.376
  rectangle net NetLED8_3: -4.224,14.714 -1.706,15.256
  rectangle net L_GND: -4.165,15.604 -1.647,16.146
  rectangle net NetLED8_3: -10.261,12.937 -7.743,13.479
  rectangle net BAT: -10.175,13.834 -7.657,14.376
  rectangle net NetLED2_1: -10.32,14.734 -7.802,15.276
  rectangle net L_GND: -10.261,15.604 -7.743,16.146
  rectangle net L_GND: -10.261,19.16 -7.743,19.702
  rectangle net NetLED2_3: -10.105,19.965 -7.587,20.507
  rectangle net BAT: -10.157,20.724 -7.639,21.266
  rectangle net NetLED2_1: -10.261,21.573 -7.743,22.115
  rectangle net NetLED2_3: -4.312,21.324 -1.794,21.866
  rectangle net BAT: -4.292,20.43 -1.774,20.972
  rectangle net NetLED3_3: -4.292,19.668 -1.774,20.21
  rectangle net L_GND: -4.292,18.779 -1.774,19.321
  rectangle net BAT: 1.8,20.574 4.318,21.116
  rectangle net NetLED4_3: 1.677,19.668 4.195,20.21
  rectangle net L_GND: 1.804,18.779 4.322,19.321
  rectangle net NetLED3_3: 1.677,21.446 4.195,21.988
  rectangle net L_GND: 7.896,19.05 10.414,19.592
  rectangle net DO: 7.874,19.886 10.392,20.428
  rectangle net BAT: 7.896,20.574 10.414,21.116
  rectangle net NetLED4_3: 7.874,21.336 10.392,21.878

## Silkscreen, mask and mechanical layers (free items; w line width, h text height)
Top Overlay:
  text "stm32f103c8t6" at -8.128,41.546 h1.52
  text "8Mhz" at 6.239,37.084 h1.52 r270
Bottom Overlay:
  text "flower lamp V1.1" at 9.144,40.665 h3
  text "DAT" at 17.907,37.465 h3 r90
  text "BAT" at 20.447,37.465 h3 r90
  text "GND" at 15.154,37.383 h3 r90
  text "2024/12" at 9.146,37.244 h3
  text "RXD" at -27.813,34.798 h3 r90
  text "TXD" at -25.273,34.798 h3 r90
  text "VCC" at -22.764,34.669 h3 r90
  text "GND" at 27.401,34.671 h3 r90
  text "GND" at -20.351,34.544 h3 r90
  text "DIO" at -17.684,34.544 h3 r90
  text "CLK" at -15.017,34.544 h3 r90
  text "BAT" at 30.226,34.417 h3 r90
Mechanical 1:
  lines w0.254: 0,28.236 0,50.038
